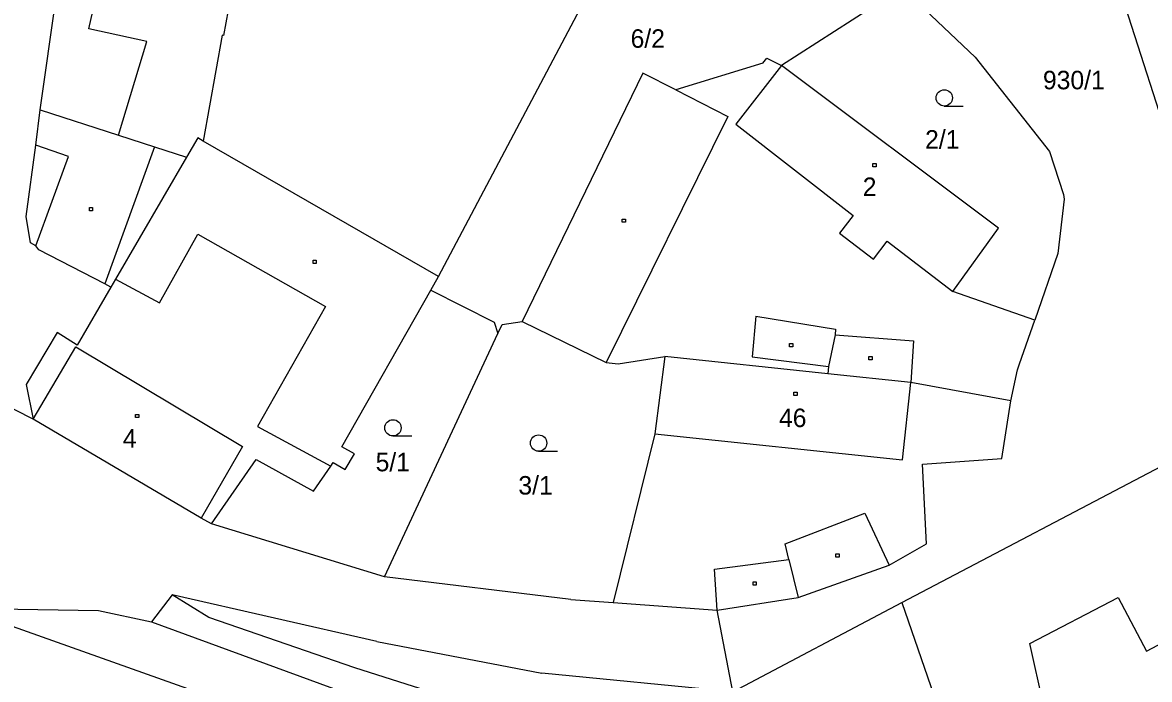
# Model space of a CAD drawing. Extents: x -796130 to -793145, y -1109506 to -1106267.
# Drawn here: x -794602 to -794498.3, y -1107830.1 to -1107769.6 of the extents above; entities that cross this region are included whole.
import ezdxf

# ---------------------------------------------------------------- set-up
doc = ezdxf.new("R2010")
doc.units = 0
for name, color, linetype in [('Vrstva 1', 7, 'Continuous'), ('Vrstva 14', 7, 'Continuous'), ('Vrstva 15', 7, 'Continuous'), ('Vrstva 2', 7, 'Continuous'), ('Vrstva 23', 7, 'Continuous'), ('Vrstva 25', 7, 'Continuous')]:
    doc.layers.add(name, color=color, linetype=linetype)

msp = doc.modelspace()

# ---------------------------------------------------------------- linework, layer by layer
at = {"layer": 'Vrstva 1'}
for p, q in [((-794488.44, -1107805.91), (-794505.52, -1107752.46)), ((-794563.76, -1107793.02), (-794546.65, -1107760.67)), ((-794582.18, -1107763.36), (-794583.53, -1107770.83)), ((-794521.06, -1107766.45), (-794532.19, -1107773.6)), ((-794521.06, -1107766.45), (-794514.36, -1107772.81)), ((-794600.41, -1107777.68), (-794598.91, -1107767.1)), ((-794583.66, -1107770.81), (-794585.42, -1107780.54)), ((-794583.53, -1107770.83), (-794583.66, -1107770.81)), ((-794533.91, -1107773.37), (-794533.52, -1107772.93)), ((-794533.52, -1107772.93), (-794532.19, -1107773.6)), ((-794514.36, -1107772.81), (-794507.5, -1107781.5)), ((-794533.91, -1107773.37), (-794541.92, -1107775.84)), ((-794512.21, -1107788.57), (-794532.19, -1107773.6)), ((-794544.95, -1107774.31), (-794556.06, -1107797.16)), ((-794541.92, -1107775.84), (-794544.95, -1107774.31)), ((-794600.83, -1107780.93), (-794600.41, -1107777.68)), ((-794585.9, -1107780.26), (-794586.94, -1107782.04)), ((-794585.42, -1107780.54), (-794585.9, -1107780.26)), ((-794601.71, -1107787.49), (-794600.83, -1107780.93)), ((-794563.76, -1107793.02), (-794585.42, -1107780.54)), ((-794586.94, -1107782.04), (-794593.49, -1107793.25)), ((-794507.5, -1107781.5), (-794506.21, -1107785.47)), ((-794506.21, -1107785.47), (-794506.16, -1107785.9)), ((-794506.16, -1107785.9), (-794506.75, -1107790.9)), ((-794601.32, -1107789.91), (-794601.71, -1107787.49)), ((-794516.41, -1107794.38), (-794512.21, -1107788.57)), ((-794600.82, -1107790.2), (-794601.32, -1107789.91)), ((-794600.54, -1107790.56), (-794600.82, -1107790.2)), ((-794594.47, -1107793.69), (-794600.54, -1107790.56)), ((-794506.75, -1107790.9), (-794508.87, -1107797.04)), ((-794593.92, -1107793.98), (-794594.47, -1107793.69)), ((-794593.49, -1107793.25), (-794593.92, -1107793.98)), ((-794564.47, -1107794.28), (-794563.76, -1107793.02)), ((-794593.92, -1107793.98), (-794597.03, -1107799.33)), ((-794572.64, -1107808.69), (-794564.47, -1107794.28)), ((-794564.47, -1107794.28), (-794558.62, -1107797.21)), ((-794508.87, -1107797.04), (-794516.41, -1107794.38)), ((-794558.62, -1107797.21), (-794558.28, -1107798.25)), ((-794558.28, -1107798.25), (-794557.89, -1107797.42)), ((-794557.89, -1107797.42), (-794556.06, -1107797.16)), ((-794556.06, -1107797.16), (-794548.33, -1107800.93)), ((-794510.26, -1107801.05), (-794508.87, -1107797.04)), ((-794598.85, -1107798.16), (-794601.7, -1107802.94)), ((-794597.03, -1107799.33), (-794598.85, -1107798.16)), ((-794568.71, -1107820.66), (-794558.28, -1107798.25)), ((-794548.33, -1107800.93), (-794547.21, -1107801.05)), ((-794547.21, -1107801.05), (-794542.93, -1107800.36)), ((-794542.93, -1107800.36), (-794543.85, -1107807.5)), ((-794527.92, -1107801.96), (-794542.93, -1107800.36)), ((-794510.45, -1107801.61), (-794510.26, -1107801.05)), ((-794520.27, -1107802.78), (-794527.92, -1107801.96)), ((-794511.07, -1107804.47), (-794510.45, -1107801.61)), ((-794601.7, -1107802.94), (-794601.08, -1107806.14)), ((-794511.07, -1107804.47), (-794520.27, -1107802.78)), ((-794601.08, -1107806.14), (-794606.66, -1107803.33)), ((-794511.89, -1107809.76), (-794511.07, -1107804.47)), ((-794585.61, -1107815.26), (-794601.08, -1107806.14)), ((-794521.11, -1107823.01), (-794491.09, -1107807.24)), ((-794543.85, -1107807.5), (-794547.67, -1107823.02)), ((-794571.49, -1107809.34), (-794572.64, -1107808.69)), ((-794572.34, -1107810.77), (-794571.49, -1107809.34)), ((-794584.64, -1107815.79), (-794580.53, -1107809.86)), ((-794580.53, -1107809.86), (-794575.25, -1107812.76)), ((-794573.66, -1107810.48), (-794573.46, -1107810.13)), ((-794573.46, -1107810.13), (-794572.34, -1107810.77)), ((-794519.2, -1107810.29), (-794511.89, -1107809.76)), ((-794518.82, -1107817.62), (-794519.2, -1107810.29)), ((-794575.25, -1107812.76), (-794573.66, -1107810.48)), ((-794584.64, -1107815.79), (-794585.61, -1107815.26)), ((-794568.71, -1107820.66), (-794584.64, -1107815.79)), ((-794522.27, -1107819.59), (-794518.82, -1107817.62)), ((-794530.63, -1107822.55), (-794522.27, -1107819.59)), ((-794551.58, -1107822.74), (-794568.71, -1107820.66)), ((-794588.28, -1107822.3), (-794590.18, -1107824.81)), ((-794584.9, -1107824.39), (-794588.28, -1107822.3)), ((-794569.43, -1107826.62), (-794588.28, -1107822.3)), ((-794551.58, -1107822.74), (-794547.67, -1107823.02)), ((-794538.11, -1107823.72), (-794530.63, -1107822.55)), ((-794607.71, -1107823.54), (-794595.06, -1107823.75)), ((-794547.69, -1107844.84), (-794607.71, -1107823.54)), ((-794595.06, -1107823.75), (-794590.18, -1107824.81)), ((-794547.67, -1107823.02), (-794538.11, -1107823.72)), ((-794536.65, -1107831.23), (-794538.11, -1107823.72)), ((-794536.65, -1107831.23), (-794521.11, -1107823.01)), ((-794590.18, -1107824.81), (-794572.51, -1107831.27)), ((-794571.46, -1107829.04), (-794584.9, -1107824.39)), ((-794569.43, -1107826.62), (-794554.24, -1107829.51)), ((-794550.76, -1107835.57), (-794571.46, -1107829.04)), ((-794536.65, -1107831.23), (-794554.24, -1107829.51))]:
    msp.add_line(p, q, dxfattribs=at)
at = {"layer": 'Vrstva 2'}
for p, q in [((-794595.94, -1107770.22), (-794595.43, -1107767.9)), ((-794590.59, -1107771.39), (-794595.94, -1107770.22)), ((-794593.21, -1107780), (-794590.59, -1107771.39)), ((-794532.19, -1107773.6), (-794536.37, -1107778.98)), ((-794541.92, -1107775.84), (-794537.12, -1107778.27)), ((-794600.41, -1107777.68), (-794593.21, -1107780)), ((-794537.12, -1107778.27), (-794548.33, -1107800.93)), ((-794536.37, -1107778.98), (-794525.58, -1107787.4)), ((-794593.21, -1107780), (-794589.89, -1107781.08)), ((-794597.81, -1107781.98), (-794600.83, -1107780.93)), ((-794589.89, -1107781.08), (-794594.47, -1107793.69)), ((-794589.89, -1107781.08), (-794586.94, -1107782.04)), ((-794600.82, -1107790.2), (-794597.81, -1107781.98)), ((-794525.58, -1107787.4), (-794526.84, -1107789.01)), ((-794589.44, -1107795.44), (-794585.9, -1107789.11)), ((-794585.9, -1107789.11), (-794574.16, -1107795.77)), ((-794526.84, -1107789.01), (-794523.72, -1107791.43)), ((-794523.72, -1107791.43), (-794522.44, -1107789.76)), ((-794522.44, -1107789.76), (-794516.41, -1107794.38)), ((-794593.49, -1107793.25), (-794589.44, -1107795.44)), ((-794574.16, -1107795.77), (-794580.41, -1107806.82)), ((-794534.54, -1107796.67), (-794534.87, -1107800.42)), ((-794534.54, -1107796.67), (-794527.21, -1107797.87)), ((-794527.21, -1107797.87), (-794527.25, -1107798.37)), ((-794527.25, -1107798.37), (-794527.84, -1107801.28)), ((-794527.25, -1107798.37), (-794520.02, -1107798.92)), ((-794520.02, -1107798.92), (-794520.27, -1107802.78)), ((-794601.08, -1107806.14), (-794597.13, -1107799.5)), ((-794597.13, -1107799.5), (-794581.8, -1107808.66)), ((-794534.87, -1107800.42), (-794527.84, -1107801.28)), ((-794527.84, -1107801.28), (-794527.92, -1107801.96)), ((-794521.04, -1107809.9), (-794520.27, -1107802.78)), ((-794580.41, -1107806.82), (-794573.66, -1107810.48)), ((-794543.85, -1107807.5), (-794521.04, -1107809.9)), ((-794581.8, -1107808.66), (-794585.61, -1107815.26)), ((-794531.84, -1107817.63), (-794524.51, -1107814.8)), ((-794524.51, -1107814.8), (-794522.27, -1107819.59)), ((-794531.49, -1107819.05), (-794531.84, -1107817.63)), ((-794538.35, -1107819.96), (-794531.49, -1107819.05)), ((-794531.49, -1107819.05), (-794530.63, -1107822.55)), ((-794538.11, -1107823.72), (-794538.35, -1107819.96)), ((-794509.33, -1107826.78), (-794501.19, -1107822.55)), ((-794501.19, -1107822.55), (-794498.59, -1107827.51)), ((-794521.11, -1107823.01), (-794516.55, -1107836.12)), ((-794498.59, -1107827.51), (-794495.4, -1107825.82)), ((-794506.91, -1107837.5), (-794509.33, -1107826.78))]:
    msp.add_line(p, q, dxfattribs=at)
at = {"layer": 'Vrstva 23'}
for p, q in [((-794517.19, -1107777.32), (-794515.44, -1107777.32)), ((-794567.95, -1107807.69), (-794566.2, -1107807.69)), ((-794554.54, -1107809.09), (-794552.79, -1107809.09))]:
    msp.add_line(p, q, dxfattribs=at)
for centre in [(-794517.19, -1107776.57), (-794567.95, -1107806.94), (-794554.54, -1107808.34)]:
    msp.add_circle(centre, 0.75, dxfattribs=at)
at = {"layer": 'Vrstva 25'}
for p, q in [((-794523.76, -1107782.61), (-794523.46, -1107782.61)), ((-794523.76, -1107782.91), (-794523.76, -1107782.61)), ((-794523.46, -1107782.91), (-794523.76, -1107782.91)), ((-794523.46, -1107782.61), (-794523.46, -1107782.91)), ((-794595.89, -1107786.66), (-794595.59, -1107786.66)), ((-794595.89, -1107786.96), (-794595.89, -1107786.66)), ((-794595.59, -1107786.96), (-794595.89, -1107786.96)), ((-794595.59, -1107786.66), (-794595.59, -1107786.96)), ((-794546.84, -1107787.72), (-794546.54, -1107787.72)), ((-794546.84, -1107788.02), (-794546.84, -1107787.72)), ((-794546.54, -1107788.02), (-794546.84, -1107788.02)), ((-794546.54, -1107787.72), (-794546.54, -1107788.02)), ((-794575.3, -1107791.5), (-794575, -1107791.5)), ((-794575.3, -1107791.8), (-794575.3, -1107791.5)), ((-794575, -1107791.5), (-794575, -1107791.8)), ((-794575, -1107791.8), (-794575.3, -1107791.8)), ((-794531.45, -1107799.18), (-794531.15, -1107799.18)), ((-794531.45, -1107799.48), (-794531.45, -1107799.18)), ((-794531.15, -1107799.48), (-794531.45, -1107799.48)), ((-794531.15, -1107799.18), (-794531.15, -1107799.48)), ((-794524.13, -1107800.37), (-794523.83, -1107800.37)), ((-794524.13, -1107800.67), (-794524.13, -1107800.37)), ((-794523.83, -1107800.67), (-794524.13, -1107800.67)), ((-794523.83, -1107800.37), (-794523.83, -1107800.67)), ((-794531.03, -1107803.66), (-794530.73, -1107803.66)), ((-794531.03, -1107803.96), (-794531.03, -1107803.66)), ((-794530.73, -1107803.96), (-794531.03, -1107803.96)), ((-794530.73, -1107803.66), (-794530.73, -1107803.96)), ((-794591.65, -1107805.7), (-794591.35, -1107805.7)), ((-794591.65, -1107806), (-794591.65, -1107805.7)), ((-794591.35, -1107806), (-794591.65, -1107806)), ((-794591.35, -1107805.7), (-794591.35, -1107806)), ((-794527.18, -1107818.53), (-794526.88, -1107818.53)), ((-794527.18, -1107818.83), (-794527.18, -1107818.53)), ((-794526.88, -1107818.53), (-794526.88, -1107818.83)), ((-794526.88, -1107818.83), (-794527.18, -1107818.83)), ((-794534.8, -1107821.12), (-794534.5, -1107821.12)), ((-794534.8, -1107821.42), (-794534.8, -1107821.12)), ((-794534.5, -1107821.42), (-794534.8, -1107821.42)), ((-794534.5, -1107821.12), (-794534.5, -1107821.42))]:
    msp.add_line(p, q, dxfattribs=at)

# ---------------------------------------------------------------- texts
at = {"layer": 'Vrstva 14'}
for s, p in [('6/2', (-794546.07, -1107771.96)), ('930/1', (-794508.11, -1107775.78)), ('2/1', (-794518.96, -1107781.24)), ('5/1', (-794569.54, -1107810.94)), ('3/1', (-794556.4, -1107813.08))]:
    msp.add_text(s, height=1.7, dxfattribs=at).set_placement(p)
at = {"layer": 'Vrstva 15'}
for s, p in [('2', (-794524.7, -1107785.6)), ('46', (-794532.41, -1107806.87)), ('4', (-794592.81, -1107808.76))]:
    msp.add_text(s, height=1.7, dxfattribs=at).set_placement(p)

doc.saveas('drawing.dxf')
